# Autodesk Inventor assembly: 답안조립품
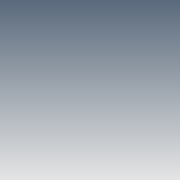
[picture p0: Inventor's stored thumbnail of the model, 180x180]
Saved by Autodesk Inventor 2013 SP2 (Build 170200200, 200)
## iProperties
Created: 2023-12
Part Number: 답안조립품
Document SubType Name: Assembly
Designer: i
Author: i
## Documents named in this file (1)
- C:\Users\i\Desktop\731208V1010\답안조립품.iam
